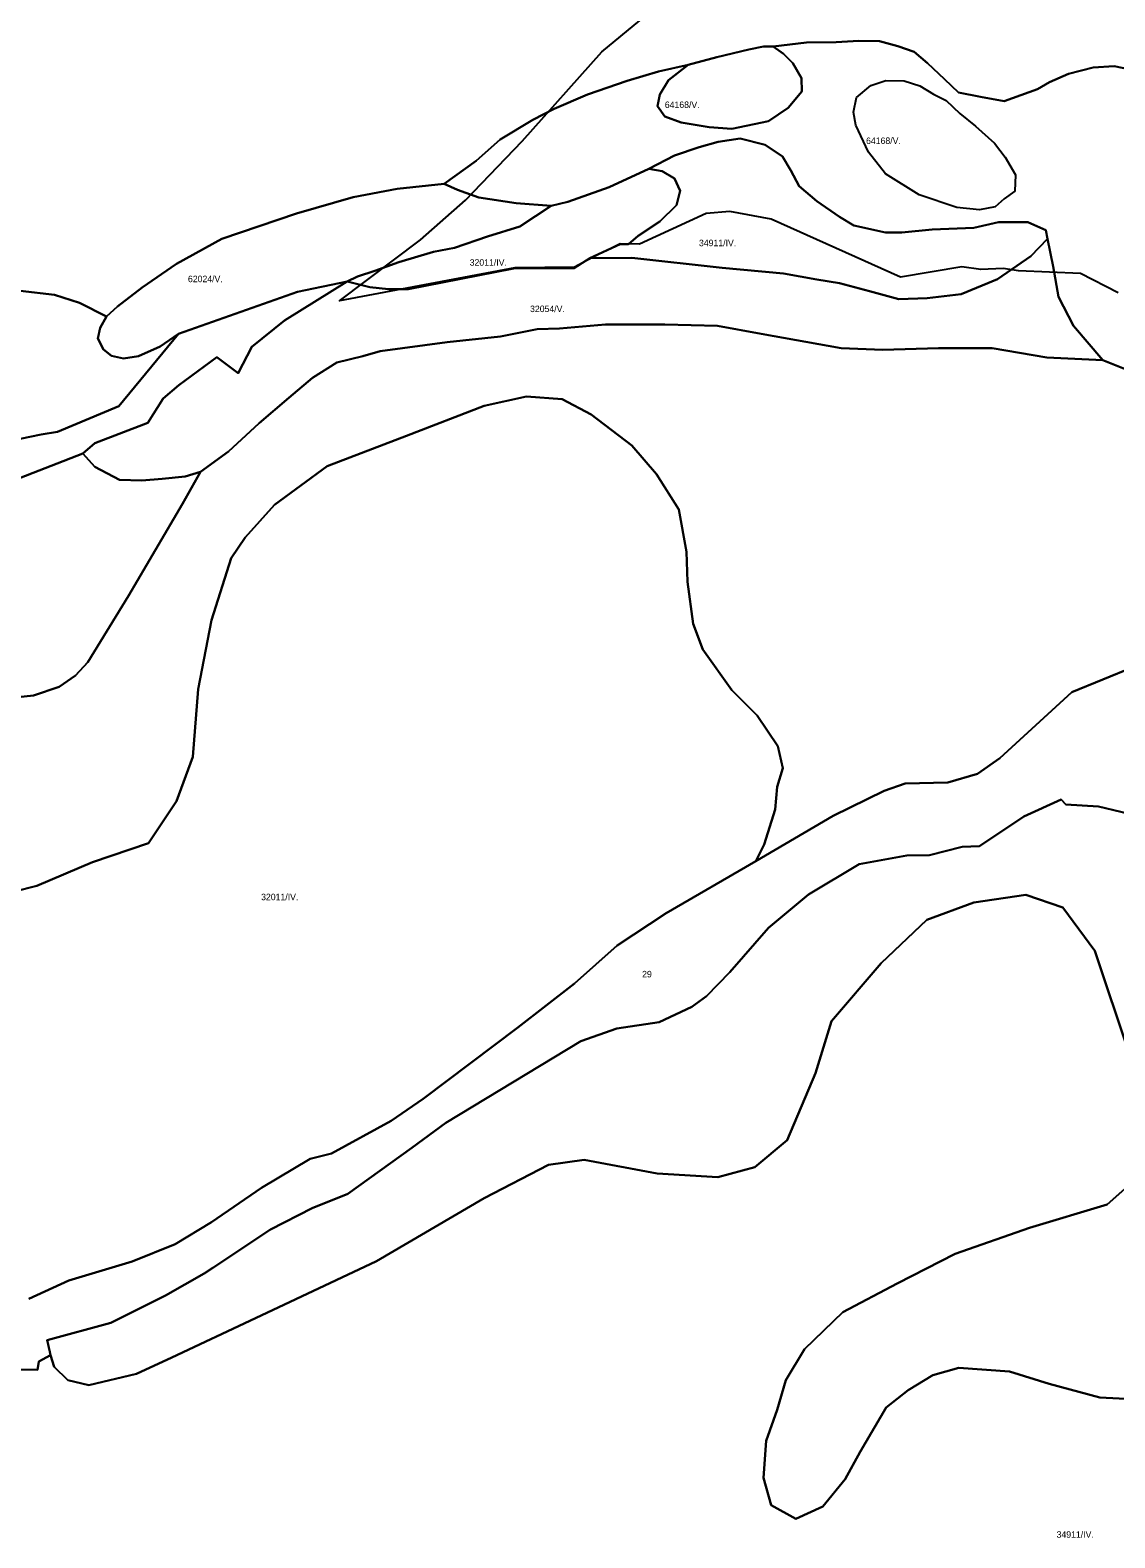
# Model space of a CAD drawing. Extents: x -521621 to -516761, y -1190184 to -1184927.
# Drawn here: x -518405 to -517738, y -1186930 to -1186003 of the extents above; entities that cross this region are included whole.
import ezdxf

# ---------------------------------------------------------------- set-up
doc = ezdxf.new("R2010")
doc.units = 0
doc.layers.add('BPEJ_s', color=7, linetype='Continuous')
doc.layers.add('odvodneni_s', color=7, linetype='Continuous')

msp = doc.modelspace()

# ---------------------------------------------------------------- linework, layer by layer
at = {"layer": 'BPEJ_s'}
for points in [[(-517723.47, -1186027.82), (-517738.12, -1186024.66), (-517751.18, -1186025.57), (-517766.28, -1186029.4), (-517778.07, -1186034.66), (-517785.38, -1186038.88), (-517805.91, -1186046.19), (-517820.53, -1186043.66), (-517834.02, -1186040.84), (-517842.74, -1186032.69), (-517853.14, -1186022.84), (-517861.3, -1186015.81), (-517871.42, -1186012.43), (-517882.67, -1186009.34), (-517895.32, -1186009.05), (-517909.38, -1186009.9), (-517927.65, -1186010.18), (-517948.18, -1186012.71), (-517954.08, -1186012.71), (-517963.08, -1186014.4), (-517982.76, -1186019.18), (-518000.47, -1186023.97), (-518018.75, -1186027.9), (-518037.87, -1186033.81), (-518062.33, -1186042.25), (-518082.86, -1186050.97), (-518096.07, -1186057.73), (-518116.03, -1186069.82), (-518130.93, -1186083.05), (-518150.62, -1186097.11), (-518179.58, -1186100.21), (-518206.57, -1186105.27), (-518241.43, -1186115.4), (-518287.54, -1186130.87), (-518315.38, -1186146.34), (-518336.47, -1186160.97), (-518351.65, -1186172.51), (-518358.4, -1186178.7), (-518374.99, -1186170.26), (-518390.45, -1186165.48), (-518411.54, -1186162.94)], [(-517724.74, -1186213.79), (-517745.18, -1186205.51), (-517763.2, -1186184.56), (-517772.44, -1186166.54), (-517775.85, -1186148.03), (-517779.26, -1186130.98), (-517780.23, -1186125.62), (-517791.43, -1186120.75), (-517809.44, -1186120.75), (-517824.54, -1186124.16), (-517850.34, -1186125.14), (-517868.84, -1186127.08), (-517879.06, -1186127.08), (-517898.53, -1186122.7), (-517907.3, -1186117.34), (-517921.18, -1186107.8), (-517932.15, -1186098.52), (-517937.21, -1186088.95), (-517942.27, -1186080.23), (-517952.96, -1186073.2), (-517968.42, -1186069.26), (-517981.92, -1186071.23), (-517993.73, -1186074.6), (-518008.91, -1186079.67), (-518024.65, -1186087.83), (-518049.12, -1186099.08), (-518074.42, -1186108.08), (-518084.82, -1186110.62), (-518106.19, -1186108.93), (-518129.25, -1186105.55), (-518142.46, -1186100.77), (-518150.62, -1186097.11), (-518130.93, -1186083.05), (-518116.03, -1186069.82), (-518096.07, -1186057.73), (-518082.86, -1186050.97), (-518062.33, -1186042.25), (-518037.87, -1186033.81), (-518018.75, -1186027.9), (-518000.47, -1186023.97), (-518012.56, -1186033.25), (-518017.91, -1186042.25), (-518019.31, -1186049.29), (-518014.81, -1186055.76), (-518004.69, -1186059.41), (-517987.54, -1186062.23), (-517973.48, -1186063.35), (-517950.99, -1186058.57), (-517938.9, -1186050.41), (-517930.46, -1186040.28), (-517930.75, -1186032.12), (-517936.09, -1186022.84), (-517941.71, -1186017.21), (-517948.18, -1186012.71), (-517927.65, -1186010.18), (-517909.38, -1186009.9), (-517895.32, -1186009.05), (-517882.67, -1186009.34), (-517871.42, -1186012.43), (-517861.3, -1186015.81), (-517853.14, -1186022.84), (-517842.74, -1186032.69), (-517834.02, -1186040.84), (-517820.53, -1186043.66), (-517805.91, -1186046.19), (-517785.38, -1186038.88), (-517778.07, -1186034.66), (-517766.28, -1186029.4), (-517751.18, -1186025.57), (-517738.12, -1186024.66), (-517723.47, -1186027.82)], [(-518502.28, -1186272.68), (-518398.58, -1186251.24), (-518388.54, -1186249.6), (-518350.76, -1186233.82), (-518314.06, -1186189.3), (-518240.84, -1186163.54), (-518210.39, -1186157.15), (-518248.83, -1186181.17), (-518269.07, -1186197.45), (-518277.37, -1186213.57), (-518290.59, -1186203.73), (-518314, -1186220.9), (-518323.49, -1186229.17), (-518332.99, -1186244.14), (-518365.52, -1186256.64), (-518373.06, -1186263.06), (-518462.29, -1186297.62)], [(-518411.54, -1186162.94), (-518390.45, -1186165.48), (-518374.99, -1186170.26), (-518358.4, -1186178.7), (-518362.33, -1186185.73), (-518363.74, -1186192.2), (-518360.37, -1186198.95), (-518355.3, -1186202.89), (-518347.99, -1186204.58), (-518338.72, -1186203.17), (-518325.5, -1186197.27), (-518314.06, -1186189.3), (-518350.76, -1186233.82), (-518388.54, -1186249.6), (-518398.58, -1186251.24), (-518502.28, -1186272.68)], [(-518424.75, -1186414.18), (-518403.38, -1186411.93), (-518387.64, -1186406.58), (-518377.52, -1186399.55), (-518369.85, -1186391.33), (-518344.96, -1186350.52), (-518311.57, -1186294), (-518300.57, -1186274.34), (-518283.33, -1186261.69), (-518264.49, -1186244.25), (-518246.21, -1186228.78), (-518231.59, -1186216.4), (-518216.69, -1186207.11), (-518200.66, -1186203.17), (-518189.98, -1186200.08), (-518148.78, -1186194.48), (-518115.95, -1186191.11), (-518093.26, -1186186.51), (-518079.63, -1186186.03), (-518051.4, -1186183.59), (-518014.88, -1186183.59), (-517982.27, -1186184.56), (-517955.49, -1186189.44), (-517906.32, -1186198.2), (-517880.52, -1186199.18), (-517846.44, -1186198.2), (-517813.34, -1186198.2), (-517779.75, -1186204.05), (-517745.18, -1186205.51), (-517724.74, -1186213.79)], [(-518442.01, -1186539.22), (-518401.39, -1186529.05), (-518367.11, -1186514.45), (-518332.52, -1186502.7), (-518315.38, -1186476.97), (-518305.23, -1186449.66), (-518302.05, -1186408.06), (-518293.8, -1186365.51), (-518281.74, -1186327.4), (-518273.17, -1186314.7), (-518255.08, -1186294.69), (-518222.71, -1186270.88), (-518173.84, -1186252.14), (-518125.91, -1186233.72), (-518099.89, -1186228), (-518077.99, -1186229.59), (-518060.22, -1186239.12), (-518035.15, -1186258.17), (-518019.91, -1186275.64), (-518006.26, -1186297.55), (-518001.5, -1186323.59), (-518000.87, -1186342.01), (-517997.38, -1186367.73), (-517991.35, -1186383.61), (-517973.58, -1186408.7), (-517958.02, -1186424.26), (-517945.33, -1186442.99), (-517942.16, -1186456.65), (-517945.65, -1186468.08), (-517946.92, -1186482.05), (-517953.58, -1186503.65), (-517958.84, -1186513.72), (-518014.04, -1186545.82), (-518044.12, -1186565.67), (-518070.38, -1186589.16), (-518105.19, -1186616.07), (-518163.5, -1186659.99), (-518183.31, -1186673.59), (-518220.01, -1186693.57), (-518233.13, -1186696.95), (-518262.99, -1186714.7), (-518293.79, -1186735.96), (-518316.22, -1186749.43), (-518342.54, -1186760.21), (-518381.71, -1186771.88), (-518406.33, -1186783.1)], [(-517707.01, -1186386.47), (-517764.3, -1186409.9), (-517808.67, -1186450.41), (-517822.33, -1186460.12), (-517840.6, -1186465.48), (-517866.88, -1186466.11), (-517879.79, -1186470.53), (-517911.12, -1186485.97), (-517958.84, -1186513.72), (-517953.58, -1186503.65), (-517946.92, -1186482.05), (-517945.65, -1186468.08), (-517942.16, -1186456.65), (-517945.33, -1186442.99), (-517958.02, -1186424.26), (-517973.58, -1186408.7), (-517991.35, -1186383.61), (-517997.38, -1186367.73), (-518000.87, -1186342.01), (-518001.5, -1186323.59), (-518006.26, -1186297.55), (-518019.91, -1186275.64), (-518035.15, -1186258.17), (-518060.22, -1186239.12), (-518077.99, -1186229.59), (-518099.89, -1186228), (-518125.91, -1186233.72), (-518173.84, -1186252.14), (-518222.71, -1186270.88), (-518255.08, -1186294.69), (-518273.17, -1186314.7), (-518281.74, -1186327.4), (-518293.8, -1186365.51), (-518302.05, -1186408.06), (-518305.23, -1186449.66), (-518315.38, -1186476.97), (-518332.52, -1186502.7), (-518367.11, -1186514.45), (-518401.39, -1186529.05), (-518442.01, -1186539.22)], [(-518462.29, -1186297.62), (-518373.06, -1186263.06), (-518365.71, -1186271.26), (-518350.52, -1186279.14), (-518336.75, -1186279.7), (-518324.1, -1186278.57), (-518310.04, -1186277.17), (-518300.57, -1186274.34), (-518311.57, -1186294), (-518344.96, -1186350.52), (-518369.85, -1186391.33), (-518377.52, -1186399.55), (-518387.64, -1186406.58), (-518403.38, -1186411.93), (-518424.75, -1186414.18)], [(-518406.33, -1186783.1), (-518381.71, -1186771.88), (-518342.54, -1186760.21), (-518316.22, -1186749.43), (-518293.79, -1186735.96), (-518262.99, -1186714.7), (-518233.13, -1186696.95), (-518220.01, -1186693.57), (-518183.31, -1186673.59), (-518163.5, -1186659.99), (-518105.19, -1186616.07), (-518070.38, -1186589.16), (-518044.12, -1186565.67), (-518014.04, -1186545.82), (-517958.84, -1186513.72), (-517911.12, -1186485.97), (-517879.79, -1186470.53), (-517866.88, -1186466.11), (-517840.6, -1186465.48), (-517822.33, -1186460.12), (-517808.67, -1186450.41), (-517764.3, -1186409.9), (-517707.01, -1186386.47)], [(-517720.36, -1186486.68), (-517747.87, -1186480.09), (-517768, -1186478.87), (-517770.79, -1186475.88), (-517793.73, -1186486.26), (-517821.06, -1186504.63), (-517831.83, -1186505.03), (-517851.97, -1186510.22), (-517865.93, -1186510.42), (-517895.2, -1186515.6), (-517926.37, -1186534.26), (-517951.06, -1186554.93), (-517974.73, -1186582.19), (-517989.16, -1186596.95), (-517998.24, -1186603.5), (-518018.2, -1186612.88), (-518044.36, -1186616.82), (-518066.39, -1186624.5), (-518149.53, -1186674.86), (-518170.5, -1186690.08), (-518209.87, -1186718.44), (-518231.94, -1186727.4), (-518257.59, -1186740.34), (-518292.98, -1186764.02), (-518298.35, -1186767.41), (-518322.21, -1186780.98), (-518355.75, -1186797.77), (-518394.91, -1186808.57), (-518393.36, -1186815.67), (-518392.84, -1186817.75), (-518400.1, -1186821.56), (-518400.97, -1186826.76), (-518432.75, -1186826.64)], [(-517728.74, -1186632.84), (-517750.05, -1186568.88), (-517769.83, -1186542.23), (-517792.66, -1186534.61), (-517824.62, -1186539.18), (-517853.54, -1186549.84), (-517881.7, -1186576.49), (-517912.13, -1186612.28), (-517922.03, -1186644.26), (-517939.53, -1186685.38), (-517959.31, -1186702.13), (-517982.14, -1186708.22), (-518019.43, -1186705.94), (-518064.33, -1186697.56), (-518086.39, -1186700.61), (-518125.97, -1186721.17), (-518192.17, -1186760), (-518266.74, -1186795.02), (-518318.31, -1186819.19), (-518340.01, -1186829.15), (-518369.28, -1186836.12), (-518382.23, -1186833.13), (-518390.59, -1186824.97), (-518392.84, -1186817.75), (-518393.36, -1186815.67), (-518394.91, -1186808.57), (-518355.75, -1186797.77), (-518322.21, -1186780.98), (-518298.35, -1186767.41), (-518292.98, -1186764.02), (-518257.59, -1186740.34), (-518231.94, -1186727.4), (-518209.87, -1186718.44), (-518170.5, -1186690.08), (-518149.53, -1186674.86), (-518066.39, -1186624.5), (-518044.36, -1186616.82), (-518018.2, -1186612.88), (-517998.24, -1186603.5), (-517989.16, -1186596.95), (-517974.73, -1186582.19), (-517951.06, -1186554.93), (-517926.37, -1186534.26), (-517895.2, -1186515.6), (-517865.93, -1186510.42), (-517851.97, -1186510.22), (-517831.83, -1186505.03), (-517821.06, -1186504.63), (-517793.73, -1186486.26), (-517770.79, -1186475.88), (-517768, -1186478.87), (-517747.87, -1186480.09), (-517720.36, -1186486.68)], [(-518432.75, -1186826.64), (-518400.97, -1186826.76), (-518400.1, -1186821.56), (-518392.84, -1186817.75), (-518390.59, -1186824.97), (-518382.23, -1186833.13), (-518369.28, -1186836.12), (-518340.01, -1186829.15), (-518318.31, -1186819.19), (-518266.74, -1186795.02), (-518192.17, -1186760), (-518125.97, -1186721.17), (-518086.39, -1186700.61), (-518064.33, -1186697.56), (-518019.43, -1186705.94), (-517982.14, -1186708.22), (-517959.31, -1186702.13), (-517939.53, -1186685.38), (-517922.03, -1186644.26), (-517912.13, -1186612.28), (-517881.7, -1186576.49), (-517853.54, -1186549.84), (-517824.62, -1186539.18), (-517792.66, -1186534.61), (-517769.83, -1186542.23), (-517750.05, -1186568.88), (-517728.74, -1186632.84)], [(-517703.63, -1186846.04), (-517747.01, -1186843.76), (-517778.2, -1186835.38), (-517802.56, -1186827.77), (-517833.76, -1186825.48), (-517849.74, -1186830.05), (-517864.95, -1186839.19), (-517878.65, -1186849.85), (-517894.63, -1186877.26), (-517903.76, -1186894.01), (-517917.46, -1186910.76), (-517934.2, -1186918.37), (-517949.42, -1186910), (-517953.99, -1186893.25), (-517952.47, -1186870.4), (-517945.62, -1186851.37), (-517940.29, -1186833.09), (-517928.88, -1186814.06), (-517905.29, -1186791.22), (-517871.8, -1186773.7), (-517836.04, -1186755.43), (-517790.38, -1186739.44), (-517742.44, -1186724.97), (-517722.65, -1186707.46)], [(-517722.65, -1186707.46), (-517742.44, -1186724.97), (-517790.38, -1186739.44), (-517836.04, -1186755.43), (-517871.8, -1186773.7), (-517905.29, -1186791.22), (-517928.88, -1186814.06), (-517940.29, -1186833.09), (-517945.62, -1186851.37), (-517952.47, -1186870.4), (-517953.99, -1186893.25), (-517949.42, -1186910), (-517934.2, -1186918.37), (-517917.46, -1186910.76), (-517903.76, -1186894.01), (-517894.63, -1186877.26), (-517878.65, -1186849.85), (-517864.95, -1186839.19), (-517849.74, -1186830.05), (-517833.76, -1186825.48), (-517802.56, -1186827.77), (-517778.2, -1186835.38), (-517747.01, -1186843.76), (-517703.63, -1186846.04)]]:
    msp.add_lwpolyline(points, dxfattribs=at)
for points in [[(-518000.47, -1186023.97), (-517982.76, -1186019.18), (-517963.08, -1186014.4), (-517954.08, -1186012.71), (-517948.18, -1186012.71), (-517941.71, -1186017.21), (-517936.09, -1186022.84), (-517930.75, -1186032.12), (-517930.46, -1186040.28), (-517938.9, -1186050.41), (-517950.99, -1186058.57), (-517973.48, -1186063.35), (-517987.54, -1186062.23), (-518004.69, -1186059.41), (-518014.81, -1186055.76), (-518019.31, -1186049.29), (-518017.91, -1186042.25), (-518012.56, -1186033.25)], [(-517878.73, -1186033.53), (-517867.48, -1186033.81), (-517857.92, -1186036.91), (-517849.49, -1186041.97), (-517841.62, -1186045.91), (-517833.18, -1186053.79), (-517823.62, -1186061.66), (-517811.81, -1186072.07), (-517805.35, -1186080.8), (-517798.88, -1186091.49), (-517799.44, -1186101.61), (-517805.91, -1186106.4), (-517811.53, -1186111.18), (-517821.09, -1186113.15), (-517835.15, -1186111.74), (-517858.2, -1186103.86), (-517879.01, -1186090.92), (-517889.41, -1186077.7), (-517897.29, -1186061.1), (-517898.69, -1186052.94), (-517896.72, -1186043.94), (-517888.01, -1186036.62)], [(-517878.73, -1186033.53), (-517867.48, -1186033.81), (-517857.92, -1186036.91), (-517849.49, -1186041.97), (-517841.62, -1186045.91), (-517833.18, -1186053.79), (-517823.62, -1186061.66), (-517811.81, -1186072.07), (-517805.35, -1186080.8), (-517798.88, -1186091.49), (-517799.44, -1186101.61), (-517805.91, -1186106.4), (-517811.53, -1186111.18), (-517821.09, -1186113.15), (-517835.15, -1186111.74), (-517858.2, -1186103.86), (-517879.01, -1186090.92), (-517889.41, -1186077.7), (-517897.29, -1186061.1), (-517898.69, -1186052.94), (-517896.72, -1186043.94), (-517888.01, -1186036.62)], [(-518061, -1186142.84), (-518042.26, -1186134.13), (-518037.17, -1186134.19), (-518031.12, -1186129.18), (-518017.91, -1186120.18), (-518007.5, -1186110.33), (-518005.25, -1186101.33), (-518008.91, -1186093.74), (-518016.5, -1186089.24), (-518024.65, -1186087.83), (-518008.91, -1186079.67), (-517993.73, -1186074.6), (-517981.92, -1186071.23), (-517968.42, -1186069.26), (-517952.96, -1186073.2), (-517942.27, -1186080.23), (-517937.21, -1186088.95), (-517932.15, -1186098.52), (-517921.18, -1186107.8), (-517907.3, -1186117.34), (-517898.53, -1186122.7), (-517879.06, -1186127.08), (-517868.84, -1186127.08), (-517850.34, -1186125.14), (-517824.54, -1186124.16), (-517809.44, -1186120.75), (-517791.43, -1186120.75), (-517780.23, -1186125.62), (-517779.26, -1186130.98), (-517789.48, -1186141.7), (-517809.93, -1186155.82), (-517832.32, -1186165.08), (-517853.26, -1186167.52), (-517870.78, -1186168), (-517888.8, -1186163.13), (-517907.3, -1186158.26), (-517921.19, -1186155.91), (-517941.71, -1186152.26), (-517979.39, -1186148.88), (-518035.06, -1186142.69)], [(-518210.39, -1186157.15), (-518204.04, -1186154.22), (-518193.35, -1186150.56), (-518178.45, -1186145.22), (-518157.08, -1186139.03), (-518144.15, -1186136.5), (-518123.91, -1186129.47), (-518103.94, -1186123.28), (-518084.82, -1186110.62), (-518074.42, -1186108.08), (-518049.12, -1186099.08), (-518024.65, -1186087.83), (-518016.5, -1186089.24), (-518008.91, -1186093.74), (-518005.25, -1186101.33), (-518007.5, -1186110.33), (-518017.91, -1186120.18), (-518031.12, -1186129.18), (-518037.17, -1186134.19), (-518042.26, -1186134.13), (-518061, -1186142.84), (-518070.68, -1186148.97), (-518107.68, -1186149.19), (-518172.62, -1186161.96), (-518184.92, -1186161.82), (-518196.45, -1186160.69)], [(-518358.4, -1186178.7), (-518351.65, -1186172.51), (-518336.47, -1186160.97), (-518315.38, -1186146.34), (-518287.54, -1186130.87), (-518241.43, -1186115.4), (-518206.57, -1186105.27), (-518179.58, -1186100.21), (-518150.62, -1186097.11), (-518142.46, -1186100.77), (-518129.25, -1186105.55), (-518106.19, -1186108.93), (-518084.82, -1186110.62), (-518103.94, -1186123.28), (-518123.91, -1186129.47), (-518144.15, -1186136.5), (-518157.08, -1186139.03), (-518178.45, -1186145.22), (-518193.35, -1186150.56), (-518204.04, -1186154.22), (-518210.39, -1186157.15), (-518240.84, -1186163.54), (-518314.06, -1186189.3), (-518325.5, -1186197.27), (-518338.72, -1186203.17), (-518347.99, -1186204.58), (-518355.3, -1186202.89), (-518360.37, -1186198.95), (-518363.74, -1186192.2), (-518362.33, -1186185.73)], [(-518373.06, -1186263.06), (-518365.52, -1186256.64), (-518332.99, -1186244.14), (-518323.49, -1186229.17), (-518314, -1186220.9), (-518290.59, -1186203.73), (-518277.37, -1186213.57), (-518269.07, -1186197.45), (-518248.83, -1186181.17), (-518210.39, -1186157.15), (-518196.45, -1186160.69), (-518184.92, -1186161.82), (-518172.62, -1186161.96), (-518107.68, -1186149.19), (-518070.68, -1186148.97), (-518061, -1186142.84), (-518035.06, -1186142.69), (-517979.39, -1186148.88), (-517941.71, -1186152.26), (-517921.19, -1186155.91), (-517907.3, -1186158.26), (-517888.8, -1186163.13), (-517870.78, -1186168), (-517853.26, -1186167.52), (-517832.32, -1186165.08), (-517809.93, -1186155.82), (-517789.48, -1186141.7), (-517779.26, -1186130.98), (-517775.85, -1186148.03), (-517772.44, -1186166.54), (-517763.2, -1186184.56), (-517745.18, -1186205.51), (-517779.75, -1186204.05), (-517813.34, -1186198.2), (-517846.44, -1186198.2), (-517880.52, -1186199.18), (-517906.32, -1186198.2), (-517955.49, -1186189.44), (-517982.27, -1186184.56), (-518014.88, -1186183.59), (-518051.4, -1186183.59), (-518079.63, -1186186.03), (-518093.26, -1186186.51), (-518115.95, -1186191.11), (-518148.78, -1186194.48), (-518189.98, -1186200.08), (-518200.66, -1186203.17), (-518216.69, -1186207.11), (-518231.59, -1186216.4), (-518246.21, -1186228.78), (-518264.49, -1186244.25), (-518283.33, -1186261.69), (-518300.57, -1186274.34), (-518310.04, -1186277.17), (-518324.1, -1186278.57), (-518336.75, -1186279.7), (-518350.52, -1186279.14), (-518365.71, -1186271.26)]]:
    msp.add_lwpolyline(points, close=True, dxfattribs=at)
at = {"layer": 'odvodneni_s'}
msp.add_lwpolyline([(-517735.74, -1186164.22), (-517759.02, -1186152.37), (-517797.05, -1186150.63), (-517806.6, -1186149.18), (-517820.34, -1186149.76), (-517832.05, -1186148.17), (-517869.65, -1186154.54), (-517949.33, -1186118.82), (-517974.78, -1186114.19), (-517989.24, -1186115.35), (-518030.31, -1186134.29), (-518042.17, -1186134), (-518059.38, -1186142.39), (-518070.37, -1186148.46), (-518107.1, -1186148.75), (-518214.98, -1186169), (-518165.09, -1186131.54), (-518137.47, -1186107.25), (-518102.62, -1186070.95), (-518053.59, -1186016), (-517971.74, -1185948.32)], dxfattribs=at)

# ---------------------------------------------------------------- texts
at = {"layer": 'BPEJ_s'}
for s, p in [('64168/V.', (-518014.78, -1186050.46)), ('64168/V.', (-517890.92, -1186072.6)), ('34911/IV.', (-517993.76, -1186135.47)), ('32011/IV.', (-518134.89, -1186147.48)), ('62024/V.', (-518308.3, -1186157.62)), ('32054/V.', (-518097.73, -1186176.01)), ('32011/IV.', (-518263.26, -1186537.84)), ('29', (-518028.76, -1186585.32)), ('34911/IV.', (-517773.65, -1186930.07))]:
    msp.add_text(s, height=4, dxfattribs=at).set_placement(p)

doc.saveas('drawing.dxf')
